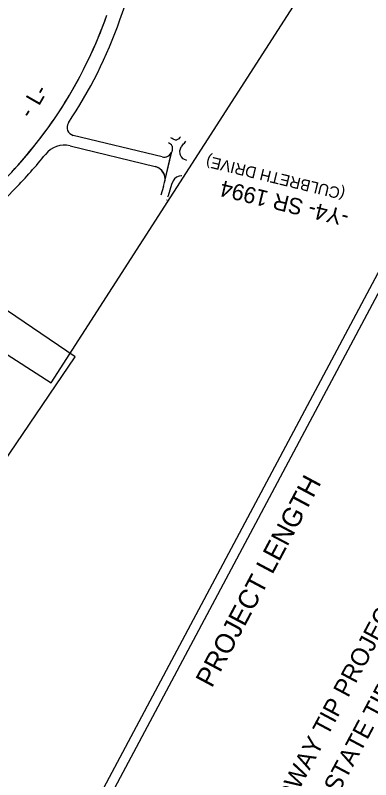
# Model space of a CAD drawing. Extents: x 1970823 to 1988115, y 770601 to 786368.
# Drawn here: x 1977005 to 1978103, y 778298 to 780658 of the extents above; entities that cross this region are included whole.
import ezdxf

# ---------------------------------------------------------------- set-up
doc = ezdxf.new("R2010")
doc.units = 0
for name, color, linetype in [('Old_Level_1', 7, 'Continuous'), ('Old_Level_3', 7, 'Continuous'), ('Prop EOT', 7, 'Continuous'), ('Prop Shade Heavy', 7, 'Continuous'), ('Sheet Title CELL', 7, 'Continuous')]:
    doc.layers.add(name, color=color, linetype=linetype)

msp = doc.modelspace()

# ---------------------------------------------------------------- linework, layer by layer
at = {"layer": 'Old_Level_1'}
for points in [[(1977116.1, 779523.4), (1977873.4, 780700.9), (1976990.2, 781268.9), (1976233, 780091.3)], [(1976403.9, 778445.7), (1977189.9, 779604.2), (1976321, 780193.7), (1975535, 779035.2)]]:
    msp.add_lwpolyline(points, close=True, dxfattribs=at)
at = {"layer": 'Old_Level_3'}
for points in [[(1977487.5, 780279.1), (1977485.8, 780279.8)], [(1977535.3, 780210.4), (1977533.1, 780210.9), (1977527.9, 780212.6), (1977523.6, 780215.3), (1977517.8, 780222)], [(1977516.1, 780163.2), (1977518.2, 780163.1), (1977511.5, 780161.9), (1977503.1, 780158.1), (1977497.1, 780153.2), (1977492.4, 780147.1), (1977488, 780135.9), (1977477, 780100.7), (1977475.6, 780096.8)], [(1977462.9, 780129.4), (1977454.1, 780102.5)], [(1977472.6, 780088.2), (1977471.8, 780086.1)]]:
    msp.add_lwpolyline(points, dxfattribs=at)
msp.add_ellipse((1977473.4, 780247.6), major_axis=(7.3, 15.9), ratio=0.997463, start_param=5.549024, end_param=6.436834, dxfattribs=at)
for points in [[(1977514.9, 780283.5), (1977509.7, 780277.4), (1977502.5, 780273.1), (1977492.5, 780276), (1977487.5, 780279.1)], [(1977517.9, 780252.3), (1977527.3, 780263.9), (1977532.2, 780269.8)], [(1977489.6, 780254.3), (1977489.2, 780239.9), (1977488.4, 780237), (1977486.5, 780233.1)], [(1977517.3, 780222.6), (1977514.5, 780229.5), (1977513.9, 780232.6), (1977513.3, 780240.2), (1977517.7, 780252.1)]]:
    msp.add_spline(points, degree=3, dxfattribs=at)
at = {"layer": 'Prop EOT'}
for p, q in [((1977328.1, 780644.1), (1977367.1, 780755)), ((1977458.6, 780221.1), (1977183.9, 780287.7)), ((1977174.4, 780255.1), (1977437.2, 780191.3)), ((1977462.9, 780129.4), (1977466.3, 780141.6))]:
    msp.add_line(p, q, dxfattribs=at)
for centre, radius, start, end in [((1975987.1, 781115.7), 1378.5, 320.501, 340.6265), ((1975987.1, 781115.7), 1421.5, 326.2491, 340.6177), ((1977189.8, 780312), 25, 146.2491, 256.3665), ((1977156.7, 780182.2), 75, 76.3665, 141.4059), ((1975987.1, 781115.7), 1378.5, 315.7395, 320.5086), ((1977464.5, 780245.4), 25, 256.3665, 338.0093), ((1975987.1, 781115.7), 1421.5, 315.7395, 321.4059), ((1977427.8, 780152.4), 40, 344.2788, 76.3665)]:
    msp.add_arc(centre, radius, start, end, dxfattribs=at)
at = {"layer": 'Prop Shade Heavy'}
for p, q in [((1977328, 780643.9), (1977367.1, 780755)), ((1977458.6, 780221.1), (1977183.9, 780287.7)), ((1977174.4, 780255.1), (1977437.2, 780191.3)), ((1977466.3, 780141.6), (1977487.7, 780236.1)), ((1977467.2, 780145.7), (1977487, 780233)), ((1976774, 779886.4), (1977005.1, 780123.6))]:
    msp.add_line(p, q, dxfattribs=at)
msp.add_lwpolyline([(1977487, 780233), (1977486.5, 780233.1), (1977486.3, 780233.2)], dxfattribs=at)
for centre, radius, start, end in [((1975987.1, 781115.7), 1378.5, 315.7395, 340.6265), ((1975987.1, 781115.7), 1421.5, 326.2491, 340.6177), ((1977189.8, 780312), 25, 146.2491, 256.3665), ((1977156.7, 780182.2), 75, 76.3665, 141.4059), ((1977464.5, 780245.4), 25, 256.3665, 330.6957), ((1975987.1, 781115.7), 1421.5, 315.7395, 321.4059), ((1977427.8, 780152.4), 40, 350.2502, 76.3665)]:
    msp.add_arc(centre, radius, start, end, dxfattribs=at)
at = {"layer": 'Sheet Title CELL'}
for p, q in [((1976163.8, 776182), (1980170.6, 783701.1)), ((1977149.7, 777968.2), (1978221.9, 779980.4))]:
    msp.add_line(p, q, dxfattribs=at)

# ---------------------------------------------------------------- texts
at = {"layer": 'Old_Level_1'}
for s, height, rotation, p in [('-', 50, 60.1322, (1977096, 780407.2)), ('L', 50, 60.1322, (1977078.4, 780376.5)), ('-', 50, 57.598, (1977053.3, 780336.5)), ('(CULBRETH DRIVE)', 35, 166.3665, (1978025.8, 780121.6)), ('-Y4- SR 1994', 50, 166.3665, (1978038.8, 780054)), ('TOTAL LENGTH STATE TIP PROJECT U-2803 = 0.809 MILES', 55, 61.9471, (1977732.4, 777744.4)), ('LENGTH ROADWAY TIP PROJECT U-2803   = 0.809 MILES', 55, 61.9471, (1977631.2, 777795.2))]:
    msp.add_text(s, height=height, rotation=rotation, dxfattribs=at).set_placement(p)
at = {"layer": 'Sheet Title CELL'}
msp.add_text('PROJECT LENGTH', height=59.998, rotation=61.9471, dxfattribs=at).set_placement((1977612.1, 778579.1))

doc.saveas('drawing.dxf')
